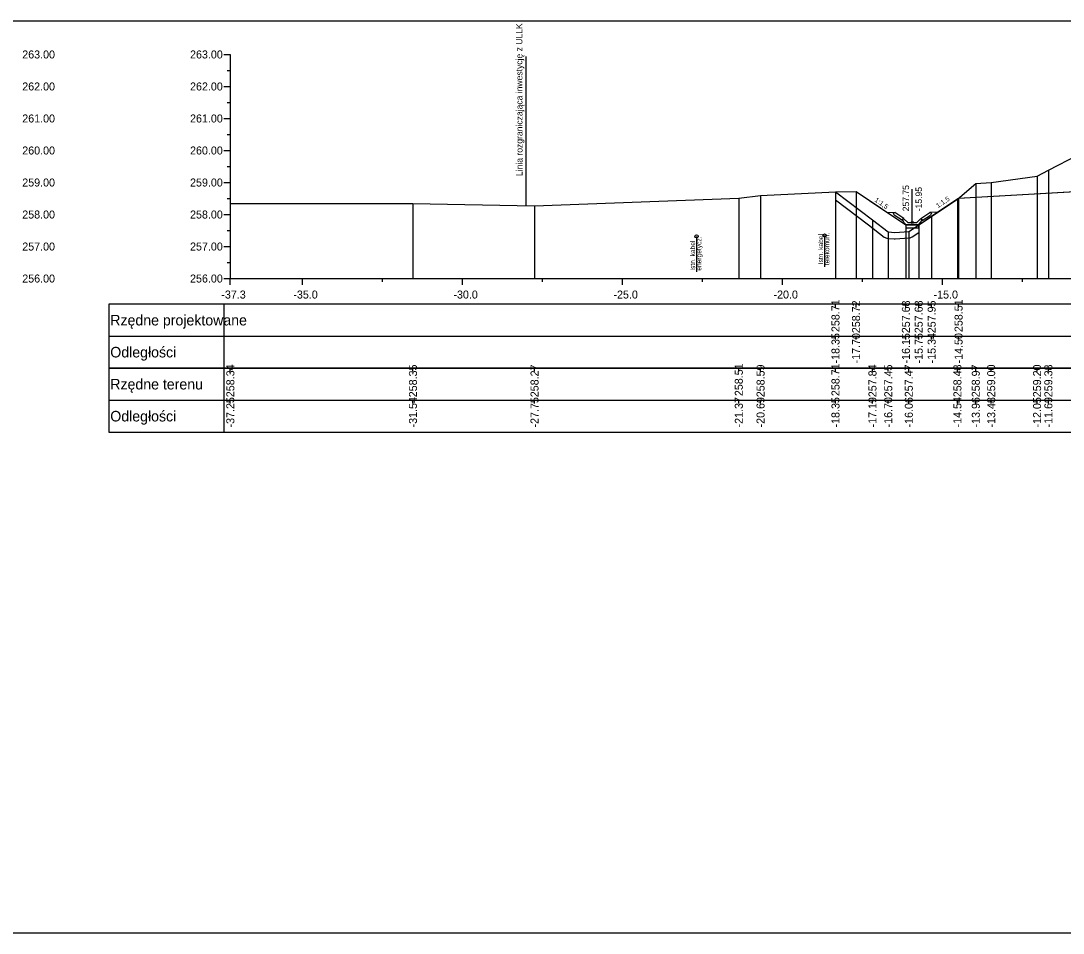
# Model space of a CAD drawing. Extents: x 6516023 to 6560129, y 5513077 to 5529206.
# Drawn here: x 6516721.42 to 6516753.98, y 5514518.16 to 5514546.66 of the extents above; entities that cross this region are included whole.
import ezdxf

# ---------------------------------------------------------------- set-up
doc = ezdxf.new("R2010")
doc.units = 0
for name, color, linetype in [('IR_default', 7, 'Continuous'), ('TOR_PRZEK_P-kable', 7, 'Continuous'), ('TOR_PRZEK_P-odwodnienie', 7, 'Continuous'), ('TOR_PRZEK_P-opisy', 7, 'Continuous'), ('TOR_PRZEK_P-schodkowanie+wymiana', 7, 'Continuous'), ('TOR_PRZEK_P-tabelka istniejace', 7, 'Continuous'), ('TOR_PRZEK_P-tabelka projektowane', 7, 'Continuous'), ('TOR_PRZEK_P-teren istniejacy', 7, 'Continuous'), ('TOR_PRZEK_P-uklad odniesienia', 7, 'Continuous'), ('TOR_PRZEK_P-warstwa ochronna II', 7, 'Continuous'), ('TOR_PS_T-granica PKP-projektowana', 7, 'Continuous'), ('TOR_RAMKI-ramka+tabelka 1', 7, 'Continuous')]:
    doc.layers.add(name, color=color, linetype=linetype)

msp = doc.modelspace()

# ---------------------------------------------------------------- linework, layer by layer
at = {"layer": 'IR_default'}
msp.add_lwpolyline([(6516746.868, 5514541.312), (6516747.51, 5514541.325), (6516748.317, 5514540.787), (6516748.489, 5514540.672), (6516749.067, 5514540.287), (6516749.159, 5514540.287), (6516749.467, 5514540.287), (6516749.56, 5514540.349), (6516749.872, 5514540.557), (6516750.068, 5514540.687), (6516750.713, 5514541.118), (6516755.094, 5514541.368)], dxfattribs=at)
at = {"layer": 'TOR_PRZEK_P-kable'}
for p, q in [((6516742.528, 5514539.923), (6516742.528, 5514538.813)), ((6516746.526, 5514539.95), (6516746.526, 5514538.976))]:
    msp.add_line(p, q, dxfattribs=at)
for centre in [(6516742.528, 5514539.923), (6516746.526, 5514539.95)]:
    msp.add_circle(centre, 0.05, dxfattribs=at)
at = {"layer": 'TOR_PRZEK_P-odwodnienie'}
for p, q in [((6516749.267, 5514540.357), (6516749.267, 5514541.401)), ((6516748.958, 5514540.416), (6516748.696, 5514540.59)), ((6516749.002, 5514540.483), (6516748.722, 5514540.669)), ((6516748.969, 5514540.433), (6516748.958, 5514540.416)), ((6516748.959, 5514540.452), (6516749.007, 5514540.476)), ((6516749.002, 5514540.483), (6516748.994, 5514540.47)), ((6516749.127, 5514540.357), (6516749.007, 5514540.476)), ((6516749.407, 5514540.357), (6516749.527, 5514540.476)), ((6516749.527, 5514540.476), (6516749.574, 5514540.452)), ((6516749.531, 5514540.483), (6516749.812, 5514540.669)), ((6516749.531, 5514540.483), (6516749.54, 5514540.47)), ((6516749.565, 5514540.433), (6516749.576, 5514540.416)), ((6516749.576, 5514540.416), (6516749.837, 5514540.59)), ((6516749.077, 5514540.287), (6516749.457, 5514540.287)), ((6516749.127, 5514540.357), (6516749.407, 5514540.357))]:
    msp.add_line(p, q, dxfattribs=at)
for points in [[(6516748.475, 5514540.681), (6516748.722, 5514540.669)], [(6516748.672, 5514540.643), (6516748.722, 5514540.669)], [(6516748.672, 5514540.643), (6516748.696, 5514540.59)], [(6516748.994, 5514540.47), (6516748.959, 5514540.451)], [(6516749.007, 5514540.357), (6516748.959, 5514540.452)], [(6516748.959, 5514540.451), (6516748.969, 5514540.433)], [(6516749.527, 5514540.357), (6516749.574, 5514540.452)], [(6516749.54, 5514540.47), (6516749.575, 5514540.451)], [(6516749.575, 5514540.451), (6516749.565, 5514540.433)], [(6516750.058, 5514540.681), (6516749.812, 5514540.669)], [(6516749.862, 5514540.643), (6516749.812, 5514540.669)], [(6516749.862, 5514540.643), (6516749.837, 5514540.59)], [(6516749.077, 5514540.287), (6516749.007, 5514540.357)], [(6516749.067, 5514540.287), (6516749.066, 5514540.287), (6516749.067, 5514540.287), (6516749.066, 5514540.286), (6516749.067, 5514540.287), (6516749.067, 5514540.286), (6516749.067, 5514540.287), (6516749.067, 5514540.287)], [(6516749.467, 5514540.287), (6516749.067, 5514540.287), (6516749.067, 5514540.187), (6516749.467, 5514540.187), (6516749.467, 5514540.287)], [(6516749.457, 5514540.287), (6516749.527, 5514540.357)], [(6516749.467, 5514540.287), (6516749.466, 5514540.287), (6516749.467, 5514540.287), (6516749.466, 5514540.286), (6516749.467, 5514540.287), (6516749.467, 5514540.286), (6516749.467, 5514540.287), (6516749.467, 5514540.287)]]:
    msp.add_lwpolyline(points, dxfattribs=at)
msp.add_circle((6516749.267, 5514540.357), 0.035, dxfattribs=at)
at = {"layer": 'TOR_PRZEK_P-schodkowanie+wymiana'}
for p, q in [((6516748.5, 5514539.86), (6516748.702, 5514539.845)), ((6516748.732, 5514539.845), (6516749.173, 5514539.878)), ((6516749.268, 5514539.911), (6516749.467, 5514540.042))]:
    msp.add_line(p, q, dxfattribs=at)
msp.add_lwpolyline([(6516746.868, 5514541.062), (6516747.901, 5514540.287), (6516748.393, 5514539.902)], dxfattribs=at)
for centre, start, end in [((6516748.516, 5514540.06), 231.9586, 265.5776), ((6516748.717, 5514540.044), 265.5776, 274.335), ((6516749.158, 5514540.077), 274.335, 303.5511)]:
    msp.add_arc(centre, 0.2, start, end, dxfattribs=at)
at = {"layer": 'TOR_PRZEK_P-tabelka istniejace'}
for p, q in [((6516724.163, 5514535.806), (6516724.163, 5514533.806)), ((6516727.763, 5514535.806), (6516727.763, 5514533.806)), ((6516727.963, 5514535.706), (6516727.963, 5514535.806)), ((6516733.668, 5514535.706), (6516733.668, 5514535.806)), ((6516737.466, 5514535.706), (6516737.466, 5514535.806)), ((6516743.847, 5514535.706), (6516743.847, 5514535.806)), ((6516744.527, 5514535.706), (6516744.527, 5514535.806)), ((6516746.868, 5514535.706), (6516746.868, 5514535.806)), ((6516748.023, 5514535.706), (6516748.023, 5514535.806)), ((6516748.516, 5514535.706), (6516748.516, 5514535.806)), ((6516749.158, 5514535.706), (6516749.158, 5514535.806)), ((6516750.677, 5514535.706), (6516750.677, 5514535.806)), ((6516751.25, 5514535.706), (6516751.25, 5514535.806)), ((6516751.732, 5514535.706), (6516751.732, 5514535.806)), ((6516753.165, 5514535.706), (6516753.165, 5514535.806)), ((6516753.518, 5514535.706), (6516753.518, 5514535.806)), ((6516724.163, 5514534.806), (6516807.963, 5514534.806)), ((6516727.963, 5514534.706), (6516727.963, 5514534.806)), ((6516733.668, 5514534.706), (6516733.668, 5514534.806)), ((6516737.466, 5514534.706), (6516737.466, 5514534.806)), ((6516743.847, 5514534.706), (6516743.847, 5514534.806)), ((6516744.527, 5514534.706), (6516744.527, 5514534.806)), ((6516746.868, 5514534.706), (6516746.868, 5514534.806)), ((6516748.023, 5514534.706), (6516748.023, 5514534.806)), ((6516748.516, 5514534.706), (6516748.516, 5514534.806)), ((6516749.158, 5514534.706), (6516749.158, 5514534.806)), ((6516750.677, 5514534.706), (6516750.677, 5514534.806)), ((6516751.25, 5514534.706), (6516751.25, 5514534.806)), ((6516751.732, 5514534.706), (6516751.732, 5514534.806)), ((6516753.165, 5514534.706), (6516753.165, 5514534.806)), ((6516753.518, 5514534.706), (6516753.518, 5514534.806))]:
    msp.add_line(p, q, dxfattribs=at)
for points in [[(6516753.165, 5514541.804), (6516753.165, 5514538.806), (6516753.165, 5514538.676), (6516753.165, 5514538.606)], [(6516753.518, 5514541.988), (6516753.518, 5514538.806), (6516753.518, 5514538.676), (6516753.518, 5514538.606)], [(6516751.25, 5514541.579), (6516751.25, 5514538.806), (6516751.25, 5514538.676), (6516751.25, 5514538.606)], [(6516751.732, 5514541.606), (6516751.732, 5514538.806), (6516751.732, 5514538.676), (6516751.732, 5514538.606)], [(6516743.847, 5514541.115), (6516743.847, 5514538.806), (6516743.847, 5514538.676), (6516743.847, 5514538.606)], [(6516744.527, 5514541.198), (6516744.527, 5514538.806), (6516744.527, 5514538.676), (6516744.527, 5514538.606)], [(6516746.868, 5514541.312), (6516746.868, 5514538.806), (6516746.868, 5514538.676), (6516746.868, 5514538.606)], [(6516750.677, 5514541.085), (6516750.677, 5514538.806), (6516750.677, 5514538.676), (6516750.677, 5514538.606)], [(6516727.963, 5514540.951), (6516727.963, 5514538.806), (6516727.963, 5514538.676), (6516727.963, 5514538.606)], [(6516733.668, 5514540.955), (6516733.668, 5514538.806), (6516733.668, 5514538.676), (6516733.668, 5514538.606)], [(6516737.466, 5514540.881), (6516737.466, 5514538.806), (6516737.466, 5514538.676), (6516737.466, 5514538.606)], [(6516748.023, 5514540.445), (6516748.023, 5514538.806), (6516748.023, 5514538.676), (6516748.023, 5514538.606)], [(6516748.516, 5514540.06), (6516748.516, 5514538.806), (6516748.516, 5514538.676), (6516748.516, 5514538.606)], [(6516749.158, 5514540.077), (6516749.158, 5514538.806), (6516749.158, 5514538.676), (6516749.158, 5514538.606)]]:
    msp.add_lwpolyline(points, dxfattribs=at)
msp.add_lwpolyline([(6516724.163, 5514535.806), (6516724.163, 5514533.806), (6516807.963, 5514533.806), (6516807.963, 5514535.806)], close=True, dxfattribs=at)
at = {"layer": 'TOR_PRZEK_P-tabelka projektowane'}
for p, q in [((6516724.163, 5514537.806), (6516724.163, 5514535.806)), ((6516727.763, 5514537.806), (6516727.763, 5514535.806)), ((6516746.868, 5514537.706), (6516746.868, 5514537.806)), ((6516747.51, 5514537.706), (6516747.51, 5514537.806)), ((6516749.067, 5514537.706), (6516749.067, 5514537.806)), ((6516749.467, 5514537.706), (6516749.467, 5514537.806)), ((6516749.872, 5514537.706), (6516749.872, 5514537.806)), ((6516750.713, 5514537.706), (6516750.713, 5514537.806)), ((6516724.163, 5514536.806), (6516807.963, 5514536.806)), ((6516746.868, 5514536.706), (6516746.868, 5514536.806)), ((6516747.51, 5514536.706), (6516747.51, 5514536.806)), ((6516749.067, 5514536.706), (6516749.067, 5514536.806)), ((6516749.467, 5514536.706), (6516749.467, 5514536.806)), ((6516749.872, 5514536.706), (6516749.872, 5514536.806)), ((6516750.713, 5514536.706), (6516750.713, 5514536.806))]:
    msp.add_line(p, q, dxfattribs=at)
for points in [[(6516746.868, 5514541.312), (6516746.868, 5514538.806), (6516746.868, 5514538.676), (6516746.868, 5514538.606)], [(6516747.51, 5514541.325), (6516747.51, 5514538.806), (6516747.51, 5514538.676), (6516747.51, 5514538.606)], [(6516750.713, 5514541.118), (6516750.713, 5514538.806), (6516750.713, 5514538.676), (6516750.713, 5514538.606)], [(6516749.872, 5514540.557), (6516749.872, 5514538.806), (6516749.872, 5514538.676), (6516749.872, 5514538.606)], [(6516749.067, 5514540.287), (6516749.067, 5514538.806), (6516749.067, 5514538.676), (6516749.067, 5514538.606)], [(6516749.467, 5514540.287), (6516749.467, 5514538.806), (6516749.467, 5514538.676), (6516749.467, 5514538.606)]]:
    msp.add_lwpolyline(points, dxfattribs=at)
msp.add_lwpolyline([(6516724.163, 5514537.806), (6516724.163, 5514535.806), (6516807.963, 5514535.806), (6516807.963, 5514537.806)], close=True, dxfattribs=at)
at = {"layer": 'TOR_PRZEK_P-teren istniejacy'}
msp.add_lwpolyline([(6516727.963, 5514540.951), (6516728.094, 5514540.948), (6516733.668, 5514540.955), (6516737.466, 5514540.881), (6516743.847, 5514541.115), (6516744.527, 5514541.198), (6516746.868, 5514541.312), (6516748.023, 5514540.445), (6516748.516, 5514540.06), (6516748.717, 5514540.044), (6516749.158, 5514540.077), (6516750.677, 5514541.085), (6516751.25, 5514541.579), (6516751.732, 5514541.606), (6516753.165, 5514541.804), (6516753.518, 5514541.988), (6516754.452, 5514542.469)], dxfattribs=at)
at = {"layer": 'TOR_PRZEK_P-uklad odniesienia'}
for p, q in [((6516727.763, 5514545.606), (6516727.963, 5514545.606)), ((6516727.963, 5514545.606), (6516727.963, 5514538.606)), ((6516727.863, 5514545.106), (6516727.963, 5514545.106)), ((6516727.763, 5514544.606), (6516727.963, 5514544.606)), ((6516727.863, 5514544.106), (6516727.963, 5514544.106)), ((6516727.763, 5514543.606), (6516727.963, 5514543.606)), ((6516727.863, 5514543.106), (6516727.963, 5514543.106)), ((6516727.763, 5514542.606), (6516727.963, 5514542.606)), ((6516727.863, 5514542.106), (6516727.963, 5514542.106)), ((6516727.763, 5514541.606), (6516727.963, 5514541.606)), ((6516727.863, 5514541.106), (6516727.963, 5514541.106)), ((6516727.763, 5514540.606), (6516727.963, 5514540.606)), ((6516727.863, 5514540.106), (6516727.963, 5514540.106)), ((6516727.763, 5514539.606), (6516727.963, 5514539.606)), ((6516727.863, 5514539.106), (6516727.963, 5514539.106)), ((6516727.763, 5514538.606), (6516727.963, 5514538.606)), ((6516727.963, 5514538.606), (6516807.963, 5514538.606)), ((6516727.963, 5514538.506), (6516727.963, 5514538.606)), ((6516727.963, 5514538.406), (6516727.963, 5514538.606)), ((6516730.213, 5514538.406), (6516730.213, 5514538.606)), ((6516732.713, 5514538.506), (6516732.713, 5514538.606)), ((6516735.213, 5514538.406), (6516735.213, 5514538.606)), ((6516737.713, 5514538.506), (6516737.713, 5514538.606)), ((6516740.213, 5514538.406), (6516740.213, 5514538.606)), ((6516742.713, 5514538.506), (6516742.713, 5514538.606)), ((6516745.213, 5514538.406), (6516745.213, 5514538.606)), ((6516747.713, 5514538.506), (6516747.713, 5514538.606)), ((6516750.213, 5514538.406), (6516750.213, 5514538.606)), ((6516752.713, 5514538.506), (6516752.713, 5514538.606))]:
    msp.add_line(p, q, dxfattribs=at)
at = {"layer": 'TOR_PRZEK_P-warstwa ochronna II'}
msp.add_lwpolyline([(6516746.868, 5514541.312), (6516747.51, 5514541.325), (6516749.067, 5514540.287), (6516749.467, 5514540.287), (6516749.872, 5514540.557), (6516750.713, 5514541.118), (6516756.534, 5514541.45), (6516757.013, 5514541.77), (6516757.591, 5514541.793), (6516765.963, 5514542.128), (6516767.238, 5514542.179), (6516768.513, 5514542.128), (6516776.407, 5514541.812), (6516777.013, 5514541.788), (6516777.492, 5514541.468), (6516779.313, 5514541.296), (6516780.438, 5514540.546), (6516780.918, 5514540.226), (6516781.318, 5514540.226), (6516782.374, 5514540.93)], dxfattribs=at)
at = {"layer": 'TOR_PS_T-granica PKP-projektowana'}
msp.add_line((6516737.202, 5514540.887), (6516737.202, 5514545.544), dxfattribs=at)
at = {"layer": 'TOR_RAMKI-ramka+tabelka 1'}
msp.add_lwpolyline([(6516634.513, 5514546.656), (6516882.013, 5514546.656), (6516882.013, 5514518.156), (6516634.513, 5514518.156)], close=True, dxfattribs=at)

# ---------------------------------------------------------------- texts
at = {"layer": 'TOR_PRZEK_P-kable'}
for s, height, p in [('energetycz.', 0.14999, (6516742.677, 5514538.85)), ('Istn. kabel', 0.14999, (6516746.481, 5514539.052)), ('telekomun.', 0.15, (6516746.675, 5514539.024)), ('Istn. kabel', 0.14999, (6516742.483, 5514538.849))]:
    msp.add_text(s, height=height, rotation=90.0511, dxfattribs=at).set_placement(p)
at = {"layer": 'TOR_PRZEK_P-odwodnienie'}
for s, p in [('257.75', (6516749.167, 5514540.707)), ('-15.95', (6516749.567, 5514540.707))]:
    msp.add_text(s, height=0.2, rotation=90, dxfattribs=at).set_placement(p)
at = {"layer": 'TOR_PRZEK_P-opisy'}
for rotation, p in [(325.9299, (6516748.073, 5514541.024)), (34.0701, (6516750.072, 5514540.802))]:
    msp.add_text('1:1,5', height=0.15, rotation=rotation, dxfattribs=at).set_placement(p)
at = {"layer": 'TOR_PRZEK_P-tabelka istniejace'}
for s, p in [('258.34', (6516728.088, 5514534.899)), ('258.35', (6516733.793, 5514534.897)), ('258.27', (6516737.591, 5514534.898)), ('258.51', (6516743.972, 5514534.933)), ('258.59', (6516744.652, 5514534.898)), ('258.71', (6516746.993, 5514534.933)), ('257.84', (6516748.148, 5514534.899)), ('257.45', (6516748.641, 5514534.897)), ('257.47', (6516749.283, 5514534.898)), ('258.48', (6516750.802, 5514534.898)), ('258.97', (6516751.375, 5514534.898)), ('259.00', (6516751.857, 5514534.898)), ('259.20', (6516753.29, 5514534.898)), ('259.38', (6516753.643, 5514534.898)), ('-37.25', (6516728.088, 5514533.953)), ('-31.54', (6516733.793, 5514533.955)), ('-27.75', (6516737.591, 5514533.953)), ('-21.37', (6516743.972, 5514533.955)), ('-20.69', (6516744.652, 5514533.955)), ('-18.35', (6516746.993, 5514533.953)), ('-17.19', (6516748.148, 5514533.955)), ('-16.70', (6516748.641, 5514533.955)), ('-16.06', (6516749.283, 5514533.954)), ('-14.54', (6516750.802, 5514533.955)), ('-13.96', (6516751.375, 5514533.954)), ('-13.48', (6516751.857, 5514533.954)), ('-12.05', (6516753.29, 5514533.953)), ('-11.69', (6516753.643, 5514533.955))]:
    msp.add_text(s, height=0.25, rotation=90, dxfattribs=at).set_placement(p)
for s, p in [('Rzędne terenu', (6516724.213, 5514535.141)), ('Odległości', (6516724.213, 5514534.141))]:
    msp.add_text(s, height=0.33, dxfattribs=at).set_placement(p)
at = {"layer": 'TOR_PRZEK_P-tabelka projektowane'}
for s, p in [('258.71', (6516746.993, 5514536.933)), ('258.72', (6516747.635, 5514536.9)), ('257.68', (6516749.192, 5514536.898)), ('257.68', (6516749.592, 5514536.898)), ('257.95', (6516749.997, 5514536.897)), ('258.51', (6516750.838, 5514536.933)), ('-18.35', (6516746.993, 5514535.953)), ('-17.70', (6516747.635, 5514535.955)), ('-16.15', (6516749.192, 5514535.953)), ('-15.75', (6516749.592, 5514535.953)), ('-15.34', (6516749.997, 5514535.955)), ('-14.50', (6516750.838, 5514535.955))]:
    msp.add_text(s, height=0.25, rotation=90, dxfattribs=at).set_placement(p)
for s, p in [('Rzędne projektowane', (6516724.213, 5514537.141)), ('Odległości', (6516724.213, 5514536.141))]:
    msp.add_text(s, height=0.33, dxfattribs=at).set_placement(p)
at = {"layer": 'TOR_PRZEK_P-uklad odniesienia'}
for s, height, p in [('263.00', 0.25, (6516721.463, 5514545.481)), ('263.00', 0.25, (6516726.705, 5514545.481)), ('262.00', 0.25, (6516721.463, 5514544.481)), ('262.00', 0.25, (6516726.705, 5514544.481)), ('261.00', 0.25, (6516721.463, 5514543.481)), ('261.00', 0.25, (6516726.705, 5514543.481)), ('260.00', 0.25, (6516721.463, 5514542.481)), ('260.00', 0.25, (6516726.705, 5514542.481)), ('259.00', 0.25, (6516721.463, 5514541.481)), ('259.00', 0.25, (6516726.705, 5514541.481)), ('258.00', 0.25, (6516721.463, 5514540.481)), ('258.00', 0.25, (6516726.705, 5514540.481)), ('257.00', 0.25, (6516721.463, 5514539.481)), ('257.00', 0.25, (6516726.705, 5514539.481)), ('256.00', 0.25, (6516721.463, 5514538.481)), ('256.00', 0.25, (6516726.705, 5514538.481)), ('-', 0.0001, (6516727.963, 5514538.606)), ('-37.3', 0.25, (6516727.682, 5514537.981)), ('-35.0', 0.25, (6516729.932, 5514537.981)), ('-30.0', 0.25, (6516734.932, 5514537.981)), ('-25.0', 0.25, (6516739.932, 5514537.981)), ('-20.0', 0.25, (6516744.932, 5514537.981)), ('-15.0', 0.25, (6516749.932, 5514537.981))]:
    msp.add_text(s, height=height, dxfattribs=at).set_placement(p)
at = {"layer": 'TOR_PS_T-granica PKP-projektowana'}
msp.add_text('Linia rozgraniczająca inwestycję z ULLK', height=0.2, rotation=90.0511, dxfattribs=at).set_placement((6516737.091, 5514541.808))

doc.saveas('drawing.dxf')
